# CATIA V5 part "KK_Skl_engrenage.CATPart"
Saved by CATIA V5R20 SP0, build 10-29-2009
Part number: Skl_engrenage
Publications: "Axe_pivot_engrenage", "Point.2", "Plan_Ref1"
Bounding box of the stored display mesh (mm): x -3 to 13, y 100 to 100, z 0 to 0
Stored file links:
  G:\Khaled_CFAO_2011\ST2M\ST2M_GR2\aandujar\Khaled\CAD_thinkMOTION\KK_Skl_engrenage.CATPart
  G:\Khaled_CFAO_2011\ST2M\ST2M_GR2\aandujar\Khaled\CAD_thinkMOTION\KK_Skl_scie_mecanique.CATProduct
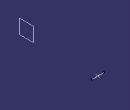
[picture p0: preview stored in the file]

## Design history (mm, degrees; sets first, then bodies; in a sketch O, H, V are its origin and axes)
WSupportSet1: ActiveGrid {3dwsupport RefPoint {point stored without definition}, 3DWOS ({wsupport Support xy-plane, RefPoint {3dwsupport}, GridIn {cartgrid Value 100, Stepbid1 0, Value 100, Stepbid2 0, Direction (1, 0, 0)}, GeometricData ({line type PtDir, Direction (1, 0, 0), Support xy-plane}; {line type PtDir, Direction (0, 1, 0), Support yz-plane})}; {wsupport Support yz-plane, RefPoint {3dwsupport}, GridIn {cartgrid Value 100, Stepbid1 0, Value 100, Stepbid2 0, Direction (0, 1, 0)}, GeometricData ({line type PtDir, Direction (0, 1, 0), Support yz-plane}; {line type PtDir, Direction (0, 0, 1), Support zx-plane})}; {wsupport Support zx-plane, RefPoint {3dwsupport}, GridIn {cartgrid Value 100, Stepbid1 0, Value 100, Stepbid2 0, Direction (0, 0, 1)}, GeometricData ({line type PtDir, Direction (0, 0, 1), Support zx-plane}; {line type PtDir, Direction (1, 0, 0), Support xy-plane})}), GeometricData ({line type PtDir, RefPoint {point stored without definition}, Direction (1, 0, 0), Support xy-plane}; {line type PtDir, RefPoint {point stored without definition}, Direction (0, 1, 0), Support yz-plane}; {line type PtDir, RefPoint {point stored without definition}, Direction (0, 0, 1), Support zx-plane})}
Set1
  Line1 "Axe_pivot_engrenage": type Normal, RefPoint Point1, RefSkin Plane1, Start -8, End 8
Set2
  Point1: linked copy from another document
  Plane1 "Plan_Ref1": linked copy from another document
Body1 (main body)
